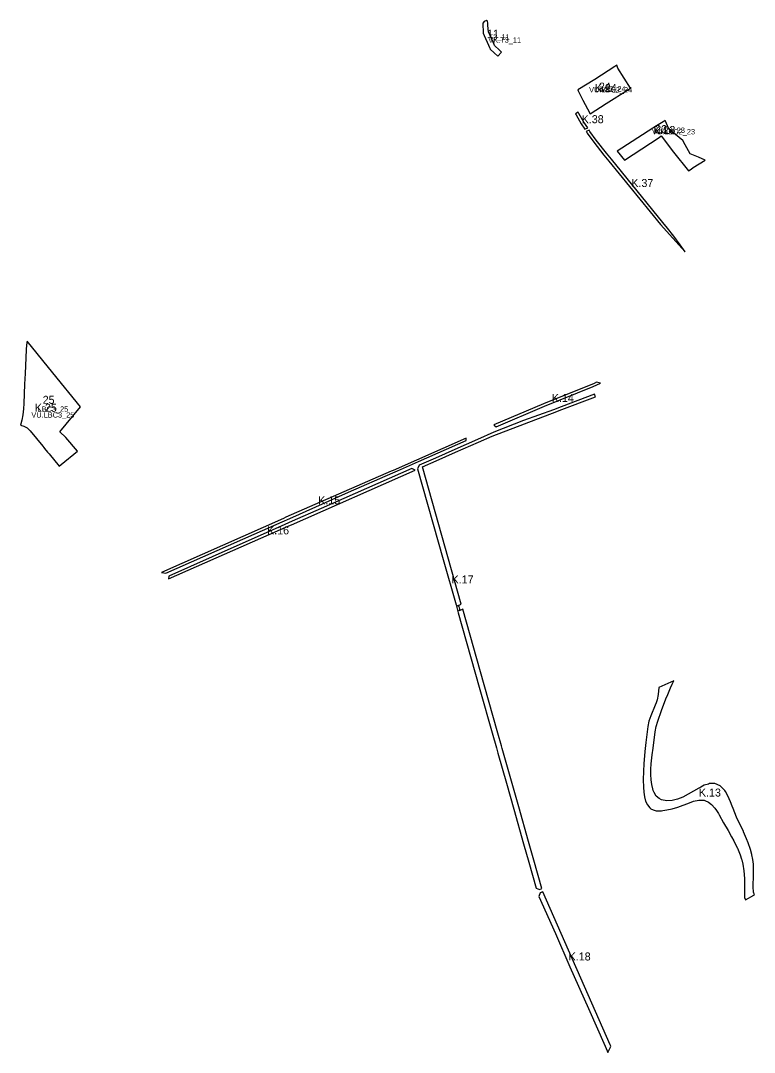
# Model space of a CAD drawing. Extents: x -521969 to -519862, y -1142171 to -1140238.
# Drawn here: x -521969 to -520594, y -1142171 to -1140238 of the extents above; entities that cross this region are included whole.
import ezdxf

# ---------------------------------------------------------------- set-up
doc = ezdxf.new("R2010")
doc.units = 0
for name, color, linetype in [('96111023', 7, 'Continuous'), ('96120023', 7, 'Continuous'), ('96140023', 7, 'Continuous'), ('96203023', 7, 'Continuous'), ('96205023', 7, 'Continuous'), ('ID_VPO', 7, 'Continuous'), ('ID_VPS', 7, 'Continuous')]:
    doc.layers.add(name, color=color, linetype=linetype)

msp = doc.modelspace()

# ---------------------------------------------------------------- linework, layer by layer
at = {"layer": '96111023'}
for points in [[(-520925.04, -1140368.05), (-520924.44, -1140369.44), (-520915.77, -1140387.04), (-520907.24, -1140403.74), (-520902.19, -1140412.67), (-520872.15, -1140393.54), (-520830.07, -1140367.42), (-520826.19, -1140365.01), (-520849.95, -1140326.96), (-520852.13, -1140321.93), (-520855.89, -1140324.19), (-520893.13, -1140348.26)], [(-520906.37, -1140439.12), (-520913.58, -1140428.33), (-520923.06, -1140411.9), (-520924.28, -1140409.64), (-520929.42, -1140412.75), (-520928.3, -1140414.82), (-520918.68, -1140431.5), (-520911.89, -1140441.66)], [(-520784.75, -1140439.67), (-520851.49, -1140482.48), (-520837.71, -1140499.35), (-520772.84, -1140457.31), (-520769.04, -1140453.82), (-520745.68, -1140484.57), (-520717.71, -1140519.42), (-520712.75, -1140516.21), (-520708.82, -1140513.67), (-520686.89, -1140499.45), (-520699.14, -1140493.81), (-520714.97, -1140487.48), (-520724, -1140470.78), (-520728.4, -1140462.65), (-520735.34, -1140457.3), (-520752.54, -1140443.09), (-520754.76, -1140441.12), (-520761.78, -1140425.25), (-520765.49, -1140427.57), (-520781.06, -1140437.3)], [(-520909.31, -1140446.06), (-520908.96, -1140446.68), (-520907.36, -1140449.12), (-520895.38, -1140466.06), (-520876.33, -1140490.04), (-520866.87, -1140501.66), (-520770.37, -1140620.36), (-520724.12, -1140671.61), (-520733.42, -1140657.97), (-520745.42, -1140642.26), (-520757.18, -1140627.06), (-520765.71, -1140616.57), (-520862.22, -1140497.87), (-520871.65, -1140486.28), (-520890.58, -1140462.46), (-520902.4, -1140445.74), (-520903.84, -1140443.54)], [(-521966.75, -1140986.81), (-521968.74, -1140996.16), (-521962.85, -1140997.93), (-521956.25, -1141001.25), (-521950.59, -1141006.47), (-521927.04, -1141035.61), (-521925.13, -1141037.95), (-521923.77, -1141039.61), (-521918.24, -1141046.46), (-521915.45, -1141049.99), (-521896.82, -1141072.9), (-521893.06, -1141069.8), (-521862.5, -1141044.56), (-521884.07, -1141019.15), (-521895.5, -1141008.4), (-521856.78, -1140962.03), (-521908.14, -1140898.33), (-521956.51, -1140838.94), (-521957.55, -1140845.37), (-521958.48, -1140855.25), (-521960.41, -1140899.15), (-521961.27, -1140919.13), (-521962.64, -1140955.52), (-521963.61, -1140965.78), (-521964.79, -1140976.78)], [(-521082.3, -1140995.42), (-521081.12, -1140996.97), (-521077.97, -1140999.02), (-520987.34, -1140960.66), (-520896.33, -1140923.45), (-520882.47, -1140917.37), (-520890.08, -1140915.49), (-520894.6, -1140917.89), (-520989.26, -1140956.04)], [(-521222.3, -1141071.25), (-521225.53, -1141078.04), (-521177.35, -1141247.92), (-521153.24, -1141332.9), (-521151.86, -1141337.89), (-521150.52, -1141342.71), (-521149.23, -1141347.36), (-521109.72, -1141486.85), (-521084.21, -1141576.91), (-521078.78, -1141596.05), (-521077.42, -1141600.82), (-521076.03, -1141605.72), (-521074.66, -1141610.52), (-521058.67, -1141667), (-521044.98, -1141715.3), (-521026.62, -1141780.12), (-521016.76, -1141814.92), (-521003.04, -1141863.38), (-520997.06, -1141866.15), (-520992.44, -1141864.11), (-521007.52, -1141810.87), (-521017.38, -1141776.07), (-521035.75, -1141711.23), (-521066.79, -1141601.67), (-521068.18, -1141596.78), (-521074.97, -1141572.8), (-521100.48, -1141482.76), (-521140.66, -1141340.91), (-521147.68, -1141344.03), (-521146.08, -1141340.6), (-521147.33, -1141335.67), (-521150.33, -1141334.27), (-521143.42, -1141331.19), (-521216.29, -1141073.97), (-521190.59, -1141062.63), (-521154.28, -1141046.62), (-521111.47, -1141027.75), (-521085.77, -1141016.42), (-520964.29, -1140970.32), (-520959.78, -1140968.46), (-520892.3, -1140942.89), (-520893.74, -1140937.98), (-520956.56, -1140961.79), (-520970.5, -1140967.09), (-521026.59, -1140987.63), (-521082.18, -1141009.47), (-521112.83, -1141022.98), (-521155.63, -1141041.85), (-521191.96, -1141057.88)], [(-521476.67, -1141170.91), (-521705, -1141272.16), (-521696.71, -1141273.51), (-521531.28, -1141200.09), (-521478.81, -1141176.87), (-521464.85, -1141170.68), (-521354.37, -1141121.84), (-521271.86, -1141085.49), (-521262.72, -1141081.47), (-521223.67, -1141064.26), (-521134.18, -1141024.63), (-521134.23, -1141020.21), (-521271.3, -1141080.74), (-521274.53, -1141082.16), (-521472.07, -1141168.66)], [(-521692.02, -1141284.07), (-521466.3, -1141184.96), (-521461.21, -1141182.74), (-521230.09, -1141080.11), (-521236.08, -1141077.32), (-521405.94, -1141152.24), (-521460.33, -1141176.23), (-521474.13, -1141182.35), (-521609.81, -1141242.59), (-521691.15, -1141278.7)], [(-520802.58, -1141660.76), (-520802.12, -1141674.39), (-520801.39, -1141683.67), (-520800.15, -1141692.43), (-520798.14, -1141700.76), (-520794.86, -1141707.13), (-520790.51, -1141712.79), (-520788.49, -1141714.55), (-520784.24, -1141716.51), (-520778.49, -1141718.29), (-520776.22, -1141718.49), (-520768.49, -1141718.49), (-520765.89, -1141718.16), (-520758.49, -1141717.01), (-520748.49, -1141714.63), (-520737.83, -1141711.42), (-520715.69, -1141703.56), (-520708.49, -1141700.66), (-520698.49, -1141698.33), (-520688.49, -1141698.8), (-520686.99, -1141699.26), (-520680.23, -1141702.5), (-520674.58, -1141706.85), (-520668.49, -1141713.61), (-520665.44, -1141717.71), (-520663.04, -1141721.47), (-520661.54, -1141723.82), (-520660.44, -1141725.82), (-520652.18, -1141740.76), (-520643.44, -1141755.72), (-520637, -1141767.42), (-520632.79, -1141775.07), (-520626.68, -1141787.7), (-520626.27, -1141788.54), (-520621.34, -1141800.76), (-520618.62, -1141809.07), (-520618.17, -1141810.44), (-520616.14, -1141818.42), (-520614.04, -1141830.76), (-520613.05, -1141845.33), (-520613.19, -1141870.76), (-520612.71, -1141880.76), (-520611.23, -1141885.62), (-520595.23, -1141876.48), (-520594.48, -1141876.16), (-520596.28, -1141870.76), (-520596.94, -1141860.76), (-520596.03, -1141838.3), (-520595.96, -1141828.23), (-520596.37, -1141818.65), (-520597.38, -1141809.66), (-520598.99, -1141801.26), (-520599.21, -1141800.48), (-520601.96, -1141790.76), (-520606.35, -1141778.69), (-520609.24, -1141770.76), (-520614.96, -1141757.69), (-520615.1, -1141757.37), (-520627.89, -1141730.76), (-520634.31, -1141714.34), (-520636.14, -1141709.65), (-520639.3, -1141701.58), (-520644.07, -1141690.76), (-520648.49, -1141682.61), (-520649.78, -1141680.76), (-520658.49, -1141671.54), (-520668.49, -1141667.34), (-520678.49, -1141667.68), (-520680.68, -1141668.57), (-520688.49, -1141670.81), (-520694.77, -1141674.48), (-520698.49, -1141676.14), (-520708.49, -1141681.73), (-520718.49, -1141687.63), (-520728.49, -1141692.76), (-520738.49, -1141696.45), (-520748.49, -1141698.92), (-520758.49, -1141699.72), (-520768.49, -1141697.8), (-520772.97, -1141695.24), (-520778.49, -1141691.03), (-520782.24, -1141684.51), (-520783.84, -1141680.76), (-520784.93, -1141677.21), (-520786.77, -1141669.05), (-520787.95, -1141660.76), (-520788.48, -1141650.77), (-520788.33, -1141640.76), (-520787.54, -1141630.76), (-520785.6, -1141613.65), (-520784.01, -1141600.98), (-520780.2, -1141570.76), (-520778.33, -1141560.76), (-520775.47, -1141550.76), (-520768.6, -1141530.76), (-520760.32, -1141508.93), (-520756.59, -1141500.76), (-520751.33, -1141487.92), (-520748.12, -1141481.13), (-520745.05, -1141475.27), (-520773.3, -1141487.53), (-520774.42, -1141500.76), (-520776.72, -1141510.76), (-520778.49, -1141516.25), (-520780.07, -1141520.76), (-520788.33, -1141540.76), (-520791.87, -1141550.76), (-520794.11, -1141560.76), (-520797.9, -1141590.76), (-520799.43, -1141607.66), (-520801.52, -1141630.76), (-520802.32, -1141644.59)], [(-520995.39, -1141872.52), (-520997.93, -1141879.1), (-520967.25, -1141948.55), (-520939.85, -1142010.61), (-520905.36, -1142088.65), (-520874.16, -1142159.29), (-520870.13, -1142168.42), (-520868.95, -1142171.08), (-520864.2, -1142161.29), (-520863.18, -1142159.4), (-520864.37, -1142156.71), (-520990.8, -1141870.5)]]:
    msp.add_lwpolyline(points, close=True, dxfattribs=at)
at = {"layer": '96120023'}
msp.add_lwpolyline([(-521092.32, -1140284.11), (-521090.43, -1140288.34), (-521089.34, -1140290.78), (-521089.05, -1140291.44), (-521081.54, -1140298.53), (-521075.22, -1140304.5), (-521068.35, -1140297.23), (-521072.76, -1140293.07), (-521080.73, -1140285.54), (-521081.11, -1140284.7), (-521081.89, -1140282.94), (-521083.79, -1140278.7), (-521092.42, -1140259.41), (-521093.43, -1140247.58), (-521093.8, -1140243.17), (-521094.12, -1140239.48), (-521096.26, -1140238.22), (-521100.42, -1140239.62), (-521102.93, -1140242.86), (-521102.76, -1140247.73), (-521102.44, -1140256.49), (-521102.24, -1140261.94), (-521100.5, -1140265.83), (-521092.32, -1140284.11)], dxfattribs=at)
at = {"layer": '96140023'}
for points in [[(-520925.04, -1140368.05), (-520924.44, -1140369.44), (-520915.77, -1140387.04), (-520907.24, -1140403.74), (-520902.19, -1140412.67), (-520872.15, -1140393.54), (-520830.07, -1140367.42), (-520826.19, -1140365.01), (-520849.95, -1140326.96), (-520852.13, -1140321.93), (-520855.89, -1140324.19), (-520893.13, -1140348.26), (-520925.04, -1140368.05)], [(-520784.75, -1140439.67), (-520851.49, -1140482.48), (-520837.71, -1140499.35), (-520772.84, -1140457.31), (-520769.04, -1140453.82), (-520745.68, -1140484.57), (-520717.71, -1140519.42), (-520712.75, -1140516.21), (-520708.82, -1140513.67), (-520686.89, -1140499.45), (-520699.14, -1140493.81), (-520714.97, -1140487.48), (-520724, -1140470.78), (-520728.4, -1140462.65), (-520735.34, -1140457.3), (-520752.54, -1140443.09), (-520754.76, -1140441.12), (-520761.78, -1140425.25), (-520765.49, -1140427.57), (-520781.06, -1140437.3), (-520784.75, -1140439.67)], [(-521966.75, -1140986.81), (-521968.74, -1140996.16), (-521962.85, -1140997.93), (-521956.25, -1141001.25), (-521950.59, -1141006.47), (-521927.04, -1141035.61), (-521925.13, -1141037.95), (-521923.77, -1141039.61), (-521918.24, -1141046.46), (-521915.45, -1141049.99), (-521896.82, -1141072.9), (-521893.06, -1141069.8), (-521862.5, -1141044.56), (-521884.07, -1141019.15), (-521895.5, -1141008.4), (-521856.78, -1140962.03), (-521908.14, -1140898.33), (-521956.51, -1140838.94), (-521957.55, -1140845.37), (-521958.48, -1140855.25), (-521960.41, -1140899.15), (-521961.27, -1140919.13), (-521962.64, -1140955.52), (-521963.61, -1140965.78), (-521964.79, -1140976.78), (-521966.75, -1140986.81)]]:
    msp.add_lwpolyline(points, dxfattribs=at)
at = {"layer": '96203023'}
msp.add_lwpolyline([(-521092.32, -1140284.11), (-521090.43, -1140288.34), (-521089.34, -1140290.78), (-521089.05, -1140291.44), (-521081.54, -1140298.53), (-521075.22, -1140304.5), (-521068.35, -1140297.23), (-521072.76, -1140293.07), (-521080.73, -1140285.54), (-521081.11, -1140284.7), (-521081.89, -1140282.94), (-521083.79, -1140278.7), (-521092.42, -1140259.41), (-521093.43, -1140247.58), (-521093.8, -1140243.17), (-521094.12, -1140239.48), (-521096.26, -1140238.22), (-521100.42, -1140239.62), (-521102.93, -1140242.86), (-521102.76, -1140247.73), (-521102.44, -1140256.49), (-521102.24, -1140261.94), (-521100.5, -1140265.83), (-521092.32, -1140284.11)], dxfattribs=at)
at = {"layer": '96205023'}
for points in [[(-520852.13, -1140321.93), (-520855.89, -1140324.19), (-520893.13, -1140348.26)], [(-520849.95, -1140326.96), (-520852.13, -1140321.93)], [(-520826.19, -1140365.01), (-520849.95, -1140326.96)], [(-520893.13, -1140348.26), (-520925.04, -1140368.05)], [(-520925.04, -1140368.05), (-520924.44, -1140369.44)], [(-520872.15, -1140393.54), (-520830.07, -1140367.42), (-520826.19, -1140365.01)], [(-520924.44, -1140369.44), (-520915.77, -1140387.04)], [(-520915.77, -1140387.04), (-520907.24, -1140403.74), (-520902.19, -1140412.67)], [(-520902.19, -1140412.67), (-520872.15, -1140393.54)], [(-520761.78, -1140425.25), (-520765.49, -1140427.57)], [(-520752.54, -1140443.09), (-520754.76, -1140441.12), (-520761.78, -1140425.25)], [(-520781.06, -1140437.3), (-520784.75, -1140439.67), (-520851.49, -1140482.48), (-520837.71, -1140499.35), (-520772.84, -1140457.31), (-520769.04, -1140453.82), (-520745.68, -1140484.57), (-520717.71, -1140519.42), (-520712.75, -1140516.21)], [(-520765.49, -1140427.57), (-520781.06, -1140437.3)], [(-520708.82, -1140513.67), (-520686.89, -1140499.45), (-520699.14, -1140493.81), (-520714.97, -1140487.48), (-520724, -1140470.78), (-520728.4, -1140462.65), (-520735.34, -1140457.3), (-520752.54, -1140443.09)], [(-520712.75, -1140516.21), (-520708.82, -1140513.67)], [(-521957.55, -1140845.37), (-521958.48, -1140855.25)], [(-521862.5, -1141044.56), (-521884.07, -1141019.15), (-521895.5, -1141008.4), (-521856.78, -1140962.03), (-521908.14, -1140898.33), (-521956.51, -1140838.94), (-521957.55, -1140845.37)], [(-521958.48, -1140855.25), (-521960.41, -1140899.15)], [(-521960.41, -1140899.15), (-521961.27, -1140919.13)], [(-521961.27, -1140919.13), (-521962.64, -1140955.52), (-521963.61, -1140965.78), (-521964.79, -1140976.78)], [(-521964.79, -1140976.78), (-521966.75, -1140986.81)], [(-521966.75, -1140986.81), (-521968.74, -1140996.16)], [(-521968.74, -1140996.16), (-521962.85, -1140997.93)], [(-521962.85, -1140997.93), (-521956.25, -1141001.25)], [(-521956.25, -1141001.25), (-521950.59, -1141006.47), (-521927.04, -1141035.61), (-521925.13, -1141037.95), (-521923.77, -1141039.61)], [(-521923.77, -1141039.61), (-521918.24, -1141046.46), (-521915.45, -1141049.99)], [(-521915.45, -1141049.99), (-521896.82, -1141072.9), (-521893.06, -1141069.8), (-521862.5, -1141044.56)]]:
    msp.add_lwpolyline(points, dxfattribs=at)

# ---------------------------------------------------------------- texts
at = {"layer": '96111023'}
for s, rotation, p in [('K.24', 0, (-520893.4, -1140371.92)), ('K.38', 360, (-520917.98, -1140430.36)), ('K.23', 0, (-520783.72, -1140450.57)), ('K.37', 0, (-520824.99, -1140549.89)), ('K.14', 0, (-520973.9, -1140952.69)), ('K.25', 0, (-521942.22, -1140970.98)), ('K.15', 360, (-521411.51, -1141144.3)), ('K.16', 360, (-521507.25, -1141200.68)), ('K.17', 0, (-521161.65, -1141292.63)), ('K.13', 360, (-520698.39, -1141691.87)), ('K.18', 360, (-520942.38, -1141998.95))]:
    msp.add_text(s, height=15, rotation=rotation, dxfattribs=at).set_placement(p)
at = {"layer": '96120023'}
msp.add_text('T3_11', height=10, rotation=360, dxfattribs=at).set_placement((-521091.8, -1140273.71))
at = {"layer": '96140023'}
for s, rotation, p in [('LBC2_24', 0, (-520893.01, -1140371)), ('LBC2_23', 360, (-520782.01, -1140448.54)), ('LBC3_25', 360, (-521937.17, -1140970.94))]:
    msp.add_text(s, height=10, rotation=rotation, dxfattribs=at).set_placement(p)
at = {"layer": '96203023'}
msp.add_text('VK.T3_11', height=10, rotation=360, dxfattribs=at).set_placement((-521092.8, -1140279.52))
at = {"layer": '96205023'}
for s, p in [('VU.LBC2_24', (-520903.97, -1140372.71)), ('VU.LBC2_23', (-520786.13, -1140451.39)), ('VU.LBC3_25', (-521948.66, -1140981.88))]:
    msp.add_text(s, height=10, rotation=0, dxfattribs=at).set_placement(p)
at = {"layer": 'ID_VPO'}
for s, rotation, p in [('24', 0, (-520885.67, -1140369.33)), ('23', 360, (-520780.19, -1140449.07)), ('25', 0, (-521927.46, -1140956.11))]:
    msp.add_text(s, height=15, rotation=rotation, dxfattribs=at).set_placement(p)
at = {"layer": 'ID_VPS'}
msp.add_text('11', height=15, rotation=360, dxfattribs=at).set_placement((-521095.39, -1140270.42))

doc.saveas('drawing.dxf')
